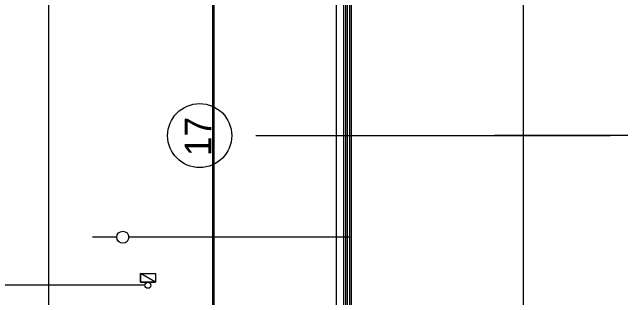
# Model space of a CAD drawing. Extents: x -264222 to -263592, y -1242345 to -1242048.
# Drawn here: x -263925.35 to -263905.16, y -1242194.27 to -1242184.78 of the extents above; entities that cross this region are included whole.
import ezdxf

# ---------------------------------------------------------------- set-up
doc = ezdxf.new("R2010")
doc.units = 0
for name, color, linetype in [('HESCON_OSI_STAVBY_KFA', 7, 'Continuous'), ('KFA_2D_SITUACIA_DSP', 7, 'Continuous'), ('KFA_SO_62-1_VO_TRASA_KABLOV_PROJEKT', 7, 'Continuous')]:
    doc.layers.add(name, color=color, linetype=linetype)

msp = doc.modelspace()

# ---------------------------------------------------------------- linework, layer by layer
at = {"layer": 'HESCON_OSI_STAVBY_KFA'}
for p, q in [((-263908.393, -1242083.237), (-263908.393, -1242246.707)), ((-263917.265, -1242188.882), (-263905.505, -1242188.882)), ((-263917.265, -1242188.882), (-263905.505, -1242188.882)), ((-263792.653, -1242188.882), (-263909.343, -1242188.882))]:
    msp.add_line(p, q, dxfattribs=at)
msp.add_circle((-263919.125, -1242188.882), 1.064, dxfattribs=at)
at = {"layer": 'KFA_2D_SITUACIA_DSP'}
for p, q in [((-263924.143, -1242082.64), (-263924.143, -1242185.14)), ((-263914.218, -1242196.332), (-263914.218, -1242132.432)), ((-263924.143, -1242185.14), (-263924.143, -1242250.14)), ((-263921.877, -1242192.257), (-263922.677, -1242192.257)), ((-263915.293, -1242192.257), (-263921.477, -1242192.257)), ((-263914.143, -1242192.257), (-263915.293, -1242192.257)), ((-263921.093, -1242193.752), (-263921.093, -1242193.462)), ((-263921.093, -1242193.462), (-263920.593, -1242193.462)), ((-263920.593, -1242193.752), (-263921.093, -1242193.462)), ((-263920.593, -1242193.752), (-263921.093, -1242193.462)), ((-263921.093, -1242193.462), (-263921.093, -1242193.752)), ((-263920.593, -1242193.462), (-263920.593, -1242193.752)), ((-263920.944, -1242193.852), (-263925.798, -1242193.852)), ((-263920.593, -1242193.752), (-263921.093, -1242193.752)), ((-263921.093, -1242193.752), (-263920.593, -1242193.752))]:
    msp.add_line(p, q, dxfattribs=at)
for points in [[(-263794.893, -1242227.382), (-263808.968, -1242241.457), (-263894.968, -1242241.457), (-263909.043, -1242227.382), (-263909.043, -1242196.333), (-263914.143, -1242196.333), (-263914.143, -1242132.433), (-263909.043, -1242132.433), (-263909.043, -1242101.382), (-263894.968, -1242087.307), (-263808.968, -1242087.307), (-263794.893, -1242101.382), (-263794.893, -1242227.382)], [(-263918.489, -1242164.132), (-263914.1, -1242168.521), (-263914.1, -1242199.486), (-263910.004, -1242203.582), (-263891.768, -1242203.582)], [(-263918.593, -1242164.382), (-263914.35, -1242168.625), (-263914.35, -1242199.59), (-263910.108, -1242203.832), (-263891.768, -1242203.832)], [(-263918.696, -1242164.632), (-263914.6, -1242168.728), (-263914.6, -1242199.693), (-263910.211, -1242204.082), (-263891.768, -1242204.082)]]:
    msp.add_lwpolyline(points, dxfattribs=at)
msp.add_lwpolyline([(-263893.618, -1242118.282), (-263916.093, -1242118.282), (-263916.093, -1242175.482), (-263914.293, -1242175.482), (-263914.293, -1242210.482), (-263893.618, -1242210.482), (-263893.618, -1242166.382), (-263900.043, -1242166.382), (-263900.043, -1242162.382), (-263893.618, -1242162.382)], close=True, dxfattribs=at)
for centre, radius in [((-263921.677, -1242192.257), 0.2), ((-263920.844, -1242193.852), 0.1)]:
    msp.add_circle(centre, radius, dxfattribs=at)
at = {"layer": 'KFA_SO_62-1_VO_TRASA_KABLOV_PROJEKT'}
for p, q in [((-263918.645, -1242194.9), (-263918.645, -1242084.831)), ((-263918.695, -1242110.308), (-263918.695, -1242194.95))]:
    msp.add_line(p, q, dxfattribs=at)

# ---------------------------------------------------------------- texts
at = {"layer": 'HESCON_OSI_STAVBY_KFA'}
msp.add_text('17', height=0.875, rotation=90, dxfattribs=at).set_placement((-263918.744, -1242189.562))

doc.saveas('drawing.dxf')
